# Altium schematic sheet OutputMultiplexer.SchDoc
size A4
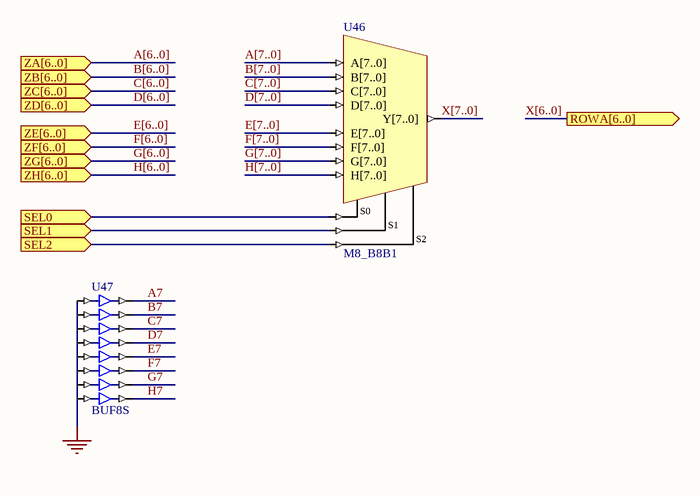
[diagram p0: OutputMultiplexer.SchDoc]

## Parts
U46  M8_B8B1
U47  BUF8S

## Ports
ROWA[6..0] (out), SEL0 (in), SEL1 (in), SEL2 (in), ZA[6..0] (in), ZB[6..0] (in), ZC[6..0] (in), ZD[6..0] (in), ZE[6..0] (in), ZF[6..0] (in), ZG[6..0] (in), ZH[6..0] (in)

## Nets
GND: U47.I0 U47.I1 U47.I2 U47.I3 U47.I4 U47.I5 U47.I6 U47.I7
A7: U47.O0
B7: U47.O1
C7: U47.O2
D7: U47.O3
E7: U47.O4
F7: U47.O5
G7: U47.O6
H7: U47.O7
SEL0: U46.S0 ; port SEL0
SEL1: U46.S1 ; port SEL1
SEL2: U46.S2 ; port SEL2

Not connected (* = marked no-connect by the designer): U46 A[7..0] B[7..0] C[7..0] D[7..0] E[7..0] F[7..0] G[7..0] H[7..0] Y[7..0]

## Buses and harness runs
bus A[6..0] = port ZA[6..0]
bus A[7..0]
bus B[6..0] = port ZB[6..0]
bus B[7..0]
bus C[6..0] = port ZC[6..0]
bus C[7..0]
bus D[6..0] = port ZD[6..0]
bus D[7..0]
bus E[6..0] = port ZE[6..0]
bus E[7..0]
bus F[6..0] = port ZF[6..0]
bus F[7..0]
bus G[6..0] = port ZG[6..0]
bus G[7..0]
bus H[6..0] = port ZH[6..0]
bus H[7..0]
bus X[6..0] = port ROWA[6..0]
bus X[7..0]

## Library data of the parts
U46 = M8_B8B1: 8x8-Bit Bus to 1x8-Bit Bus Multiplexer; ArchiveName: GENERIC
U47 = BUF8S: 8-Bit General Purpose (Non-inverting) Buffer, Single Pin Version; ArchiveName: GENERIC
